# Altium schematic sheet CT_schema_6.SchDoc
size 372 x 243 mm
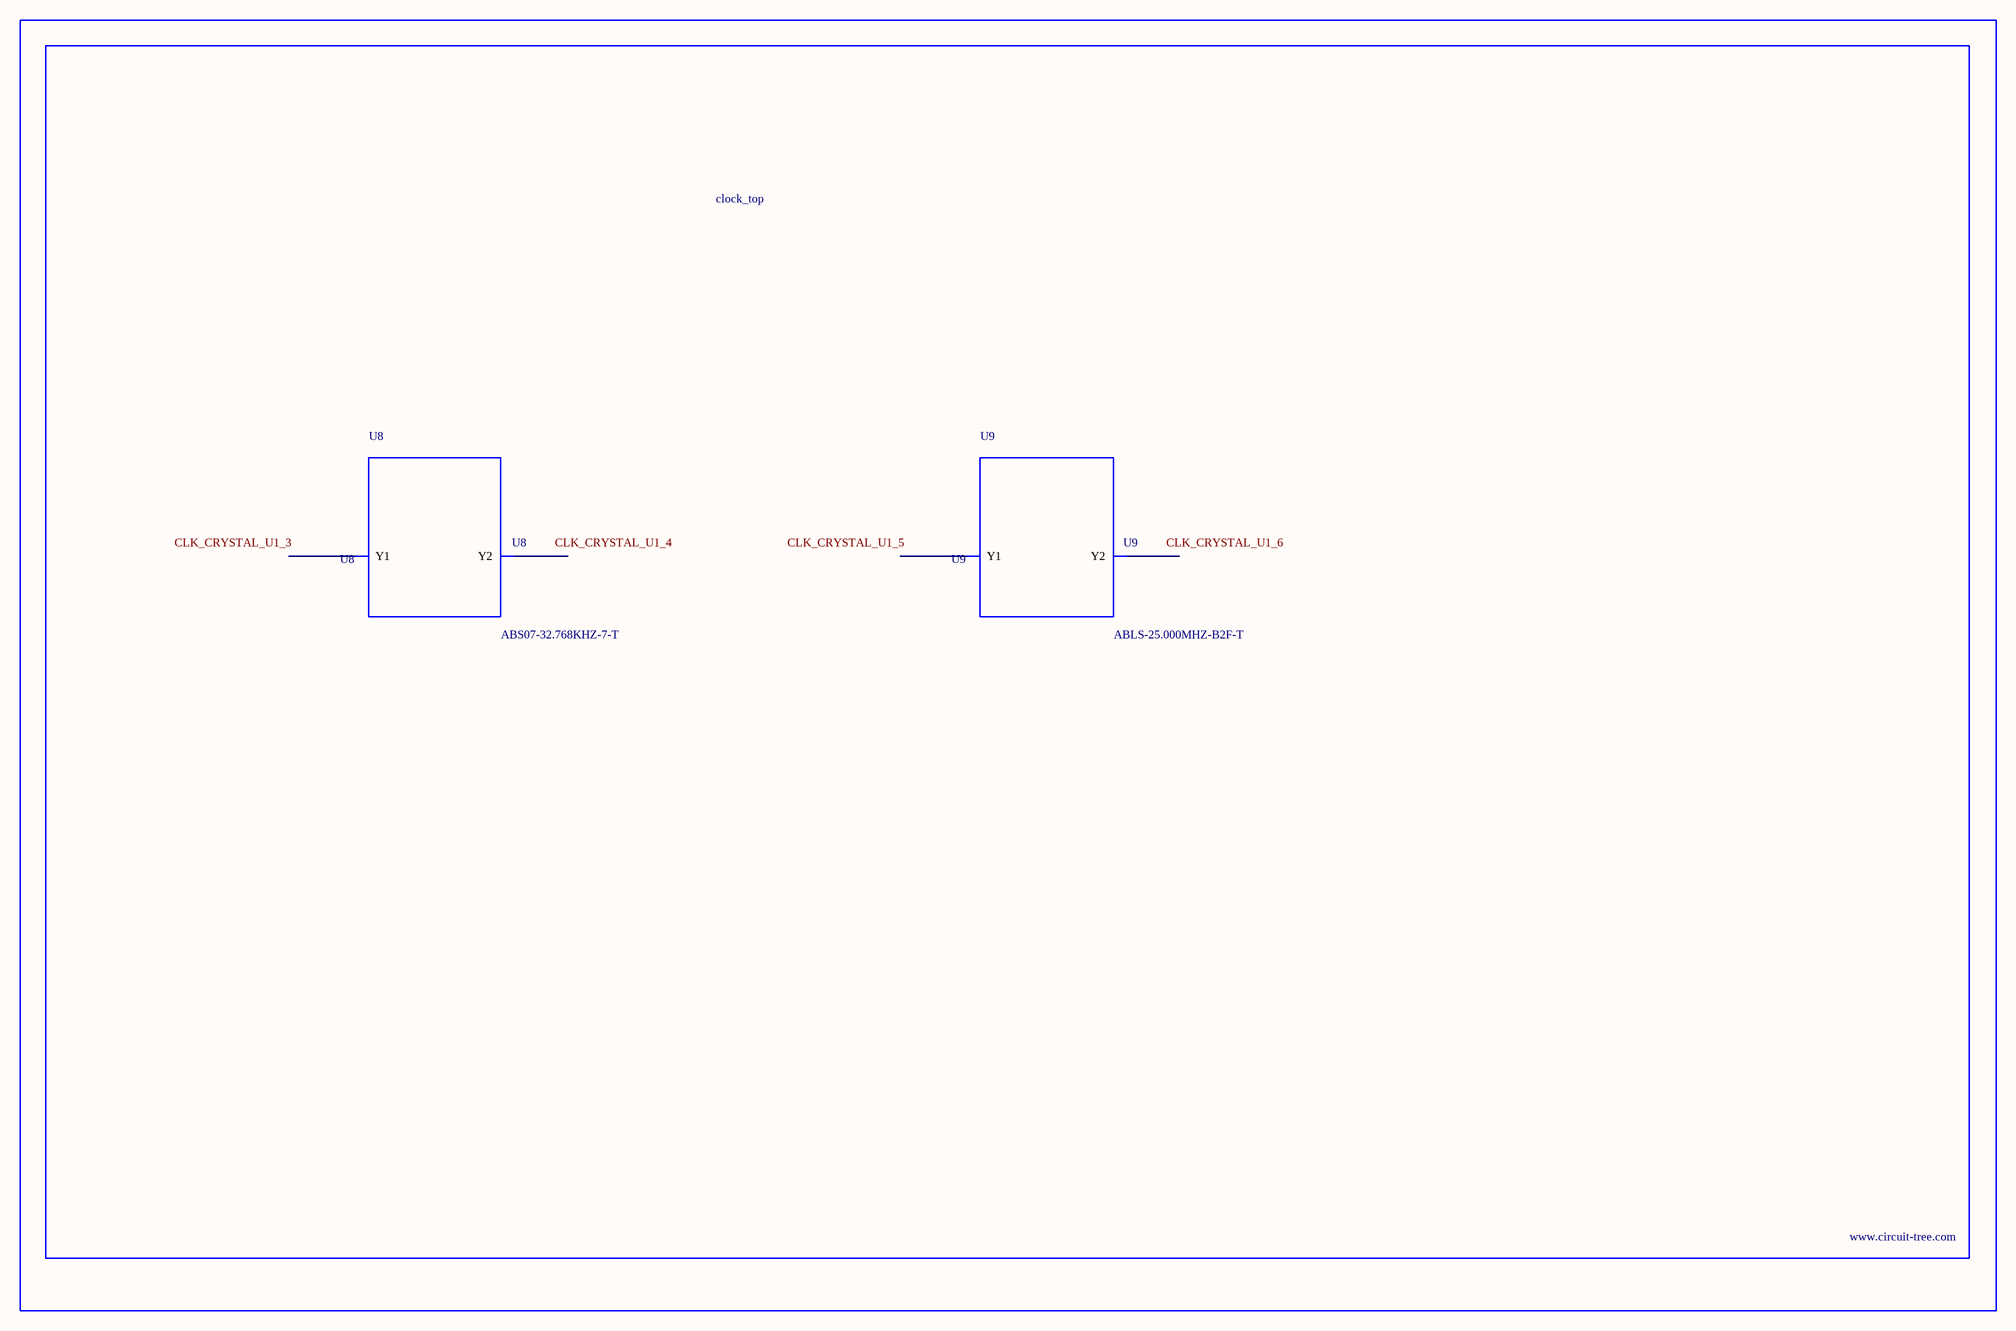
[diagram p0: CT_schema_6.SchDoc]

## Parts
BORDER5  (no value)
U8  ABS07-32.768KHZ-7-T  [ABS07-32.768KHZ-7-T]
U9  ABLS-25.000MHZ-B2F-T  [ABLS-25.000MHZ-B2F-T]

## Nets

Not connected (* = marked no-connect by the designer): U8 1(Y1) 2(Y2); U9 1(Y1) 2(Y2)

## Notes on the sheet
- Labels drawn without touching a wire or pin: CLK_CRYSTAL_U1_3, CLK_CRYSTAL_U1_4, CLK_CRYSTAL_U1_5, CLK_CRYSTAL_U1_6

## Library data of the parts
BORDER5 = BORDER_PAGE5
